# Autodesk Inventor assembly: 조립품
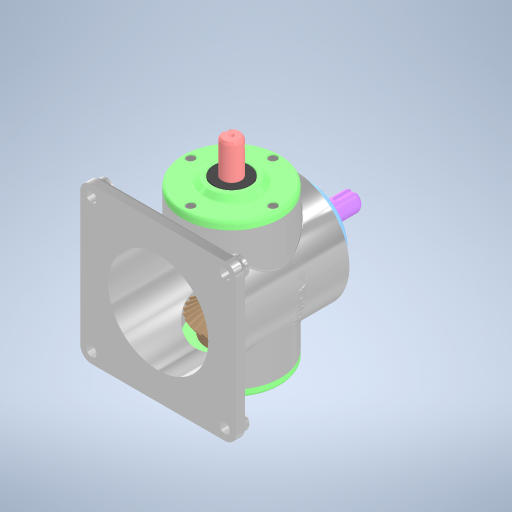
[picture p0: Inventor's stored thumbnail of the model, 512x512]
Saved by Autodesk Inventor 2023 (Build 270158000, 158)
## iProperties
Created: 2025-05
Part Number: 조립품
Document SubType Name: Assembly
Designer: ADMIN_PC
Author: ADMIN_PC
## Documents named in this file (13)
- C:\Users\ADMIN_PC\Downloads\750505V1002\조립품.iam
- C:\Users\ADMIN_PC\Downloads\750505V1002\본체.ipt
- C:\Users\ADMIN_PC\Downloads\750505V1002\측면 커버.ipt
- C:\Users\ADMIN_PC\Downloads\750505V1002\깊은 홈 볼 베어링 6203.ipt
- C:\Users\ADMIN_PC\Downloads\750505V1002\오일 실 17 32 8.ipt
- C:\Users\ADMIN_PC\Downloads\750505V1002\메인 축.ipt
- C:\Users\ADMIN_PC\Downloads\750505V1002\평행 키 5x5.ipt
- C:\Users\ADMIN_PC\Downloads\750505V1002\메인 베벨기어.ipt
- C:\Users\ADMIN_PC\Downloads\750505V1002\윗 커버.ipt
- C:\Users\ADMIN_PC\Downloads\750505V1002\6각 구멍붙이 볼트 M4-10L.ipt
- C:\Users\ADMIN_PC\Downloads\750505V1002\서브 축.ipt
- C:\Users\ADMIN_PC\Downloads\750505V1002\평행 키 4x4.ipt
- C:\Users\ADMIN_PC\Downloads\750505V1002\서브 베벨기어.ipt
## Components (12 placed, 1 different names)
1. 6각 구멍붙이 볼트 M4-10L:1
2. 6각 구멍붙이 볼트 M4-10L:2
3. 6각 구멍붙이 볼트 M4-10L:3
4. 6각 구멍붙이 볼트 M4-10L:4
5. 6각 구멍붙이 볼트 M4-10L:5
6. 6각 구멍붙이 볼트 M4-10L:6
7. 6각 구멍붙이 볼트 M4-10L:7
8. 6각 구멍붙이 볼트 M4-10L:8
9. 6각 구멍붙이 볼트 M4-10L:9
10. 6각 구멍붙이 볼트 M4-10L:10
11. 6각 구멍붙이 볼트 M4-10L:11
12. 6각 구멍붙이 볼트 M4-10L:12
